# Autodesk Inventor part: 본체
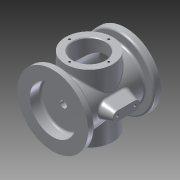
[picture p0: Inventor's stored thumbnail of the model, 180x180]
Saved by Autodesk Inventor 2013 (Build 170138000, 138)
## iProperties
Created: 2018-02
Part Number: 본체
Material: 알루미늄 6061
Document SubType Name: Modeling
Designer: Administrator
Density: 2.71 g/cm^3
Mass: 771.854 g
Surface Area: 821.824 cm^2
Volume: 284.817 cm^3
Author: Administrator
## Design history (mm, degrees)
sketch "스케치2"
  geometry: C1 r 38 at (0, 0); 1 further point
  constraints: 1 centre point, 1 coincident
  dimensions: "d0" = 38 radius of C1
extrude "돌출1" new body sketch "스케치2" stored distance "d1" = 108; taper "d2" = 0 deg
sketch "스케치3"
  geometry: C1 r 52.5 at (0, 0); 1 further point
  constraints: 1 centre point, 1 coincident
  dimensions: "d3" = 52.5 radius of C1
extrude "돌출2" join sketch "스케치3" distance "d4" = 10; taper "d5" = 0 deg
hole "구멍1" diameter "d8" = 66; stored, may be unused: countersink angle "d12" = 90 deg, drill point angle "d14" = 0 deg; dims "d9" = 6, "d10" = 74, "d11" = 7, "d13" = 86, "d113" = 10, "d114" = 10
sketch "스케치5" dims "d17" = 45
  geometry: 3 further points
  constraints: 2 vertical alignment, 1 coincident, 2 other
hole "구멍2" sketch "스케치5" at (0, 45) diameter "d18" = 3.242; stored, may be unused: countersink angle "d22" = 90 deg, drill point angle "d24" = 118 deg; dims "d19" = 4, "d20" = 90, "d21" = 7, "d23" = 6
hole "구멍3" diameter "d30" = 68; stored, may be unused: countersink angle "d34" = 90 deg, drill point angle "d36" = 0 deg; dims "d31" = 4, "d32" = 90, "d33" = 7, "d35" = 16, "d37" = 10, "d38" = 10
hole "구멍4" diameter "d41" = 10; stored, may be unused: countersink angle "d45" = 90 deg, drill point angle "d47" = 118 deg; dims "d39" = 10, "d40" = 10, "d42" = 4, "d43" = 90, "d44" = 7, "d46" = 16
node "작업 평면1"
sketch "스케치6"
  geometry: C1 r 35 at (0, 0); 1 further point
  constraints: 1 centre point, 1 coincident
  dimensions: "d49" = 35 radius of C1
extrude "돌출3" join sketch "스케치6" stored distance "d50" = 10; taper "d51" = 0 deg
hole "구멍5" diameter "d54" = 48; stored, may be unused: countersink angle "d58" = 90 deg, drill point angle "d60" = 118 deg; dims "d52" = 10, "d53" = 10, "d55" = 4, "d56" = 90, "d57" = 7, "d59" = 16
sketch "스케치7" dims "d61" = 29
  geometry: 3 further points
  constraints: 2 vertical alignment, 1 coincident, 2 other
hole "구멍6" sketch "스케치7" at (0, 29) diameter "d62" = 3.242; stored, may be unused: countersink angle "d66" = 90 deg, drill point angle "d68" = 118 deg; dims "d63" = 4, "d64" = 90, "d65" = 7, "d67" = 6
chamfer "모따기1" distance "d72" = 1; stored, may be unused: second distance "d73" = 2, angle "d74" = 45 deg
node "작업 평면2"
sketch "스케치8"
  geometry: L1 (20, 0)-(-20, 0); L2 (13, 7)-(-13, 7); L3 (-13, -7)-(13, -7); A1 r 7 centre (13, 0) between (13, -7) and (13, 7); A2 r 7 centre (-13, 0) between (-13, 7) and (-13, -7); 2 further points
  constraints: 6 end point, 6 point on circle, 4 tangent, 2 centre point, 2 coincident, 2 horizontal alignment, 1 horizontal, 1 midpoint
  dimensions: "d76" = 7 radius of A1; "d77" = 7 radius of A2; "d79" = 40 distance of L1.start L1.end
extrude "돌출4" join sketch "스케치8" stored distance "d80" = 10; taper "d81" = 15 deg
hole "구멍7" diameter "d84" = 4.134; stored, may be unused: countersink angle "d88" = 90 deg, drill point angle "d90" = 118 deg; dims "d82" = 10, "d83" = 10, "d85" = 6, "d86" = 90, "d87" = 7, "d89" = 8
hole "구멍8" diameter "d93" = 4.134; stored, may be unused: countersink angle "d97" = 90 deg, drill point angle "d99" = 118 deg; dims "d91" = 10, "d92" = 10, "d94" = 6, "d95" = 90, "d96" = 7, "d98" = 8
fillet "모깎기1" dims "d100" = 3
chamfer "모따기2" distance "d101" = 1; stored, may be unused: second distance "d102" = 2, angle "d103" = 45 deg
fillet "모깎기2" dims "d104" = 3
fillet "모깎기3" dims "d105" = 3
fillet "모깎기4" dims "d106" = 3
fillet "모깎기5" dims "d107" = 3
sketch "스케치9"
  geometry: C1 r 43 at (0, 0); 1 further point
  constraints: 1 centre point, 1 coincident, 1 other
  dimensions: "d108" = 43 radius of C1
feature "엠보싱1" sketch "스케치9" dims "d1" = 108, "d25" = 40, "d111" = 0.5, "d112" = 0
fillet "모깎기6" dims "d115" = 3
node "솔리드1"
mirror "대칭1"
pattern_circular "원형 패턴1" dims angle "d26" = 360 deg
pattern_circular "원형 패턴2" dims angle "d70" = 360 deg
mirror "대칭2"
other parameters: "d75" = 55
